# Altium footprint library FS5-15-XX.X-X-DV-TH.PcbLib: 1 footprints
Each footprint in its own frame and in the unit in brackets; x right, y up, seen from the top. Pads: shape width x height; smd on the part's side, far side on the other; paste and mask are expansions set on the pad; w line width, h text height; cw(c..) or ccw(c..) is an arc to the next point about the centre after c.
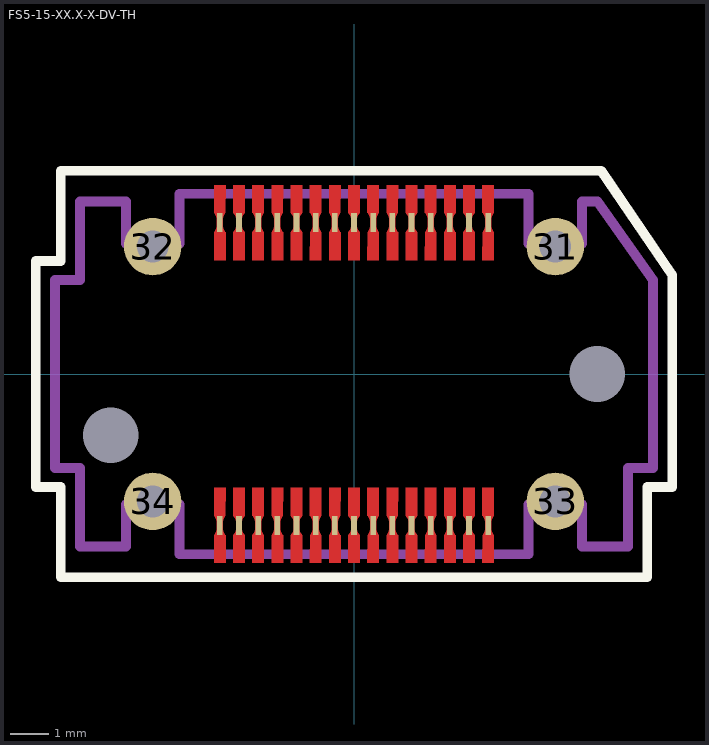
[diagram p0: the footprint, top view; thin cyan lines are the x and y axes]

## FS5-15-XX.X-X-DV-TH [mm]
pads (36):
  rect 0.15x0.5 smd: 1(3.5,3.95) 2(3.5,-3.95) 3(3,3.95) 4(3,-3.95) 5(2.5,3.95) 6(2.5,-3.95) 7(2,3.95) 8(2,-3.95) 9(1.5,3.95) 10(1.5,-3.95) 11(1,3.95) 12(1,-3.95) 13(0.5,3.95) 14(0.5,-3.95) 15(0,3.95) 16(0,-3.95) 17(-0.5,3.95) 18(-0.5,-3.95) 19(-1,3.95) 20(-1,-3.95) 21(-1.5,3.95) 22(-1.5,-3.95) 23(-2,3.95) 24(-2,-3.95) 25(-2.5,3.95) 26(-2.5,-3.95) 27(-3,3.95) 28(-3,-3.95) 29(-3.5,3.95) 30(-3.5,-3.95)
  round 1.5 hole 0.83 mask+0.075: 31(5.25,3.325) 32(-5.25,3.325) 33(5.25,-3.325) 34(-5.25,-3.325)
  round 0 hole 1.45 unplated: 35(6.35,0) 36(-6.35,-1.6)
Top Layer:
  region: -3.65,-2.97 -3.35,-2.97 -3.352,-3.698 -3.41,-3.784 -3.426,-3.862 -3.425,-3.862 -3.426,-4.038 -3.41,-4.116 -3.352,-4.202 -3.35,-4.2 -3.35,-4.93 -3.65,-4.93 -3.648,-4.202 -3.59,-4.116 -3.574,-4.038 -3.575,-4.038 -3.574,-3.862 -3.59,-3.784 -3.647,-3.698 -3.65,-3.7
  region: -3.65,4.93 -3.35,4.93 -3.352,4.202 -3.41,4.116 -3.426,4.038 -3.425,4.038 -3.426,3.862 -3.41,3.784 -3.352,3.698 -3.35,3.7 -3.35,2.97 -3.65,2.97 -3.648,3.698 -3.59,3.784 -3.574,3.862 -3.575,3.862 -3.574,4.038 -3.59,4.116 -3.647,4.202 -3.65,4.2
  region: -3.15,-2.97 -2.85,-2.97 -2.852,-3.698 -2.91,-3.784 -2.926,-3.862 -2.925,-3.862 -2.926,-4.038 -2.91,-4.116 -2.852,-4.202 -2.85,-4.2 -2.85,-4.93 -3.15,-4.93 -3.148,-4.202 -3.09,-4.116 -3.074,-4.038 -3.075,-4.038 -3.074,-3.862 -3.09,-3.784 -3.147,-3.698 -3.15,-3.7
  region: -3.15,4.93 -2.85,4.93 -2.852,4.202 -2.91,4.116 -2.926,4.038 -2.925,4.038 -2.926,3.862 -2.91,3.784 -2.852,3.698 -2.85,3.7 -2.85,2.97 -3.15,2.97 -3.148,3.698 -3.09,3.784 -3.074,3.862 -3.075,3.862 -3.074,4.038 -3.09,4.116 -3.147,4.202 -3.15,4.2
  region: -2.65,-2.97 -2.35,-2.97 -2.352,-3.698 -2.41,-3.784 -2.426,-3.862 -2.425,-3.862 -2.426,-4.038 -2.41,-4.116 -2.352,-4.202 -2.35,-4.2 -2.35,-4.93 -2.65,-4.93 -2.648,-4.202 -2.59,-4.116 -2.574,-4.038 -2.575,-4.038 -2.574,-3.862 -2.59,-3.784 -2.647,-3.698 -2.65,-3.7
  region: -2.65,4.93 -2.35,4.93 -2.352,4.202 -2.41,4.116 -2.426,4.038 -2.425,4.038 -2.426,3.862 -2.41,3.784 -2.352,3.698 -2.35,3.7 -2.35,2.97 -2.65,2.97 -2.648,3.698 -2.59,3.784 -2.574,3.862 -2.575,3.862 -2.574,4.038 -2.59,4.116 -2.647,4.202 -2.65,4.2
  region: -2.15,-2.97 -1.85,-2.97 -1.852,-3.698 -1.91,-3.784 -1.926,-3.862 -1.925,-3.862 -1.926,-4.038 -1.91,-4.116 -1.852,-4.202 -1.85,-4.2 -1.85,-4.93 -2.15,-4.93 -2.148,-4.202 -2.09,-4.116 -2.074,-4.038 -2.075,-4.038 -2.074,-3.862 -2.09,-3.784 -2.147,-3.698 -2.15,-3.7
  region: -2.15,4.93 -1.85,4.93 -1.852,4.202 -1.91,4.116 -1.926,4.038 -1.925,4.038 -1.926,3.862 -1.91,3.784 -1.852,3.698 -1.85,3.7 -1.85,2.97 -2.15,2.97 -2.148,3.698 -2.09,3.784 -2.074,3.862 -2.075,3.862 -2.074,4.038 -2.09,4.116 -2.147,4.202 -2.15,4.2
  region: -1.65,-2.97 -1.35,-2.97 -1.352,-3.698 -1.41,-3.784 -1.426,-3.862 -1.425,-3.862 -1.426,-4.038 -1.41,-4.116 -1.352,-4.202 -1.35,-4.2 -1.35,-4.93 -1.65,-4.93 -1.648,-4.202 -1.59,-4.116 -1.574,-4.038 -1.575,-4.038 -1.574,-3.862 -1.59,-3.784 -1.647,-3.698 -1.65,-3.7
  region: -1.65,4.93 -1.35,4.93 -1.352,4.202 -1.41,4.116 -1.426,4.038 -1.425,4.038 -1.426,3.862 -1.41,3.784 -1.352,3.698 -1.35,3.7 -1.35,2.97 -1.65,2.97 -1.648,3.698 -1.59,3.784 -1.574,3.862 -1.575,3.862 -1.574,4.038 -1.59,4.116 -1.647,4.202 -1.65,4.2
  region: -1.15,-2.97 -0.85,-2.97 -0.852,-3.698 -0.91,-3.784 -0.926,-3.862 -0.925,-3.862 -0.926,-4.038 -0.91,-4.116 -0.852,-4.202 -0.85,-4.2 -0.85,-4.93 -1.15,-4.93 -1.148,-4.202 -1.09,-4.116 -1.074,-4.038 -1.075,-4.038 -1.074,-3.862 -1.09,-3.784 -1.147,-3.698 -1.15,-3.7
  region: -1.15,4.93 -0.85,4.93 -0.852,4.202 -0.91,4.116 -0.926,4.038 -0.925,4.038 -0.926,3.862 -0.91,3.784 -0.852,3.698 -0.85,3.7 -0.85,2.97 -1.15,2.97 -1.148,3.698 -1.09,3.784 -1.074,3.862 -1.075,3.862 -1.074,4.038 -1.09,4.116 -1.147,4.202 -1.15,4.2
  region: -0.65,-2.97 -0.35,-2.97 -0.352,-3.698 -0.41,-3.784 -0.426,-3.862 -0.425,-3.862 -0.426,-4.038 -0.41,-4.116 -0.352,-4.202 -0.35,-4.2 -0.35,-4.93 -0.65,-4.93 -0.648,-4.202 -0.59,-4.116 -0.574,-4.038 -0.575,-4.038 -0.574,-3.862 -0.59,-3.784 -0.647,-3.698 -0.65,-3.7
  region: -0.65,4.93 -0.35,4.93 -0.352,4.202 -0.41,4.116 -0.426,4.038 -0.425,4.038 -0.426,3.862 -0.41,3.784 -0.352,3.698 -0.35,3.7 -0.35,2.97 -0.65,2.97 -0.648,3.698 -0.59,3.784 -0.574,3.862 -0.575,3.862 -0.574,4.038 -0.59,4.116 -0.647,4.202 -0.65,4.2
  region: -0.15,-2.97 0.15,-2.97 0.148,-3.698 0.09,-3.784 0.074,-3.862 0.075,-3.862 0.074,-4.038 0.09,-4.116 0.148,-4.202 0.15,-4.2 0.15,-4.93 -0.15,-4.93 -0.148,-4.202 -0.09,-4.116 -0.074,-4.038 -0.075,-4.038 -0.074,-3.862 -0.09,-3.784 -0.147,-3.698 -0.15,-3.7
  region: -0.15,4.93 0.15,4.93 0.148,4.202 0.09,4.116 0.074,4.038 0.075,4.038 0.074,3.862 0.09,3.784 0.148,3.698 0.15,3.7 0.15,2.97 -0.15,2.97 -0.148,3.698 -0.09,3.784 -0.074,3.862 -0.075,3.862 -0.074,4.038 -0.09,4.116 -0.147,4.202 -0.15,4.2
  region: 0.35,-2.97 0.65,-2.97 0.648,-3.698 0.59,-3.784 0.574,-3.862 0.575,-3.862 0.574,-4.038 0.59,-4.116 0.648,-4.202 0.65,-4.2 0.65,-4.93 0.35,-4.93 0.352,-4.202 0.41,-4.116 0.426,-4.038 0.425,-4.038 0.426,-3.862 0.41,-3.784 0.353,-3.698 0.35,-3.7
  region: 0.35,4.93 0.65,4.93 0.648,4.202 0.59,4.116 0.574,4.038 0.575,4.038 0.574,3.862 0.59,3.784 0.648,3.698 0.65,3.7 0.65,2.97 0.35,2.97 0.352,3.698 0.41,3.784 0.426,3.862 0.425,3.862 0.426,4.038 0.41,4.116 0.353,4.202 0.35,4.2
  region: 0.85,-2.97 1.15,-2.97 1.148,-3.698 1.09,-3.784 1.074,-3.862 1.075,-3.862 1.074,-4.038 1.09,-4.116 1.148,-4.202 1.15,-4.2 1.15,-4.93 0.85,-4.93 0.852,-4.202 0.91,-4.116 0.926,-4.038 0.925,-4.038 0.926,-3.862 0.91,-3.784 0.853,-3.698 0.85,-3.7
  region: 0.85,4.93 1.15,4.93 1.148,4.202 1.09,4.116 1.074,4.038 1.075,4.038 1.074,3.862 1.09,3.784 1.148,3.698 1.15,3.7 1.15,2.97 0.85,2.97 0.852,3.698 0.91,3.784 0.926,3.862 0.925,3.862 0.926,4.038 0.91,4.116 0.853,4.202 0.85,4.2
  region: 1.35,-2.97 1.65,-2.97 1.648,-3.698 1.59,-3.784 1.574,-3.862 1.575,-3.862 1.574,-4.038 1.59,-4.116 1.648,-4.202 1.65,-4.2 1.65,-4.93 1.35,-4.93 1.352,-4.202 1.41,-4.116 1.426,-4.038 1.425,-4.038 1.426,-3.862 1.41,-3.784 1.353,-3.698 1.35,-3.7
  region: 1.35,4.93 1.65,4.93 1.648,4.202 1.59,4.116 1.574,4.038 1.575,4.038 1.574,3.862 1.59,3.784 1.648,3.698 1.65,3.7 1.65,2.97 1.35,2.97 1.352,3.698 1.41,3.784 1.426,3.862 1.425,3.862 1.426,4.038 1.41,4.116 1.353,4.202 1.35,4.2
  region: 1.85,-2.97 2.15,-2.97 2.148,-3.698 2.09,-3.784 2.074,-3.862 2.075,-3.862 2.074,-4.038 2.09,-4.116 2.148,-4.202 2.15,-4.2 2.15,-4.93 1.85,-4.93 1.852,-4.202 1.91,-4.116 1.926,-4.038 1.925,-4.038 1.926,-3.862 1.91,-3.784 1.853,-3.698 1.85,-3.7
  region: 1.85,4.93 2.15,4.93 2.148,4.202 2.09,4.116 2.074,4.038 2.075,4.038 2.074,3.862 2.09,3.784 2.148,3.698 2.15,3.7 2.15,2.97 1.85,2.97 1.852,3.698 1.91,3.784 1.926,3.862 1.925,3.862 1.926,4.038 1.91,4.116 1.853,4.202 1.85,4.2
  region: 2.35,-2.97 2.65,-2.97 2.648,-3.698 2.59,-3.784 2.574,-3.862 2.575,-3.862 2.574,-4.038 2.59,-4.116 2.648,-4.202 2.65,-4.2 2.65,-4.93 2.35,-4.93 2.352,-4.202 2.41,-4.116 2.426,-4.038 2.425,-4.038 2.426,-3.862 2.41,-3.784 2.353,-3.698 2.35,-3.7
  region: 2.35,4.93 2.65,4.93 2.648,4.202 2.59,4.116 2.574,4.038 2.575,4.038 2.574,3.862 2.59,3.784 2.648,3.698 2.65,3.7 2.65,2.97 2.35,2.97 2.352,3.698 2.41,3.784 2.426,3.862 2.425,3.862 2.426,4.038 2.41,4.116 2.353,4.202 2.35,4.2
  region: 2.85,-2.97 3.15,-2.97 3.148,-3.698 3.09,-3.784 3.074,-3.862 3.075,-3.862 3.074,-4.038 3.09,-4.116 3.148,-4.202 3.15,-4.2 3.15,-4.93 2.85,-4.93 2.852,-4.202 2.91,-4.116 2.926,-4.038 2.925,-4.038 2.926,-3.862 2.91,-3.784 2.853,-3.698 2.85,-3.7
  region: 2.85,4.93 3.15,4.93 3.148,4.202 3.09,4.116 3.074,4.038 3.075,4.038 3.074,3.862 3.09,3.784 3.148,3.698 3.15,3.7 3.15,2.97 2.85,2.97 2.852,3.698 2.91,3.784 2.926,3.862 2.925,3.862 2.926,4.038 2.91,4.116 2.853,4.202 2.85,4.2
  region: 3.35,-2.97 3.65,-2.97 3.648,-3.698 3.59,-3.784 3.574,-3.862 3.575,-3.862 3.574,-4.038 3.59,-4.116 3.648,-4.202 3.65,-4.2 3.65,-4.93 3.35,-4.93 3.352,-4.202 3.41,-4.116 3.426,-4.038 3.425,-4.038 3.426,-3.862 3.41,-3.784 3.353,-3.698 3.35,-3.7
  region: 3.35,4.93 3.65,4.93 3.648,4.202 3.59,4.116 3.574,4.038 3.575,4.038 3.574,3.862 3.59,3.784 3.648,3.698 3.65,3.7 3.65,2.97 3.35,2.97 3.352,3.698 3.41,3.784 3.426,3.862 3.425,3.862 3.426,4.038 3.41,4.116 3.353,4.202 3.35,4.2
Top Overlay:
  lines w0.254: -8.3,-2.95 -8.3,2.95 -7.65,2.95 -7.65,5.3 6.45,5.3 8.3,2.588 8.3,-2.95 7.65,-2.95 7.65,-5.3 -7.65,-5.3 -7.65,-2.95 -8.3,-2.95
Top Paste:
  drawing of 31 lines, arcs and shapes, not listed
Top Solder:
  drawing of 30 lines, arcs and shapes, not listed
Mechanical 1:
  lines w0.254: -7.8,-2.45 -7.8,2.45 -7.15,2.45 -7.15,4.5 -5.95,4.5 -5.95,3.4 -4.55,3.4 -4.55,4.7 4.55,4.7 4.55,3.4 5.95,3.4 5.95,4.5 6.35,4.5 7.8,2.45 7.8,-2.45 7.15,-2.45 7.15,-4.5 5.95,-4.5 5.95,-3.4 4.55,-3.4 4.55,-4.7 -4.55,-4.7 -4.55,-3.4 -5.95,-3.4 -5.95,-4.5 -7.15,-4.5 -7.15,-2.45 -7.8,-2.45
  text "J1" at -0.446,-0.457 h0.76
